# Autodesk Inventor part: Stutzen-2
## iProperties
Shininess: 64.0
Length Units: 11269
Angle Units: 11279
Time Units: 11290
Mass Units: 11283
Length Display Precision: 3
Angle Display Precision: 2
Compacted: True
Part Number: Stutzen-2
Document SubType Name: Modeling
Created: 2005-09
Material: S 235 JR
Designer: Frank
Manufacturer: Standard
Standards Organization: Custom
Density: 0.0
Volumn: 0.0
Area: 0.0
PropertySet Name: Model Information
Control State: 0
Master: False
Checked Out: False
Author: Frank
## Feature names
1. Extrusion1
